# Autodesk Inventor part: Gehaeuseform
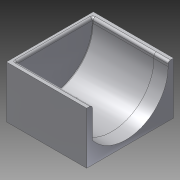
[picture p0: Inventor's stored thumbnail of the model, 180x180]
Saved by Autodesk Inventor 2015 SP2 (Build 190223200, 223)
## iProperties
Created: 2016-01
Part Number: Gehaeuseform
Material: PC/ABS-Kunststoff
Document SubType Name: Modeling
Designer: ryll
Mass: 441.159 g
Surface Area: 1593.78 cm^2
Volume: 1234.8 cm^3
Density: 0.357273 g/cm^3
Appearance: Glatt - weiß
Author: ryll
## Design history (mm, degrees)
sketch "Skizze1"
  geometry: L1 (-71, 0)-(-71, -54.491); L2 (-71, 0)-(-83, 0); L3 (-83, 0)-(-83, -100); L4 (-83, -100)-(101, -100); L5 (101, -100)-(101, 0); L6 (101, 0)-(89.5, 0); L7 (-121.405, 0)-(147.427, 0) reference; L8 (0, 22.399)-(0, -134.393) reference; A1 r 89.5 centre (0, 0) between (-71, -54.491) and (89.5, 0); 1 further point
  constraints: 12 end point, 4 perpendicular, 2 point on circle, 1 centre point, 1 coincident, 1 collinear, 1 horizontal, 1 point on line, 1 vertical
  dimensions: "d0" = 179 diameter of A1; "d1" = 71 distance from line of point (0, 0) L1; "d2" = 100 distance of L4.end L5.end; "d3" = 184 distance between parallel lines of L3 L5; "d4" = 12 distance of L1.start L2.end
extrude "Extrusion1" new body sketch "Skizze1" distance "d5" = 130; taper "d6" = 0 deg
feature "Flächenverjüngung1" dims angle "d7" = 0.01 deg
sketch "Skizze2"
  geometry: L1 (0, 101)-(-100, 101); L2 (-100, 101)-(-100, -83); L3 (-100, -83)-(0, -83); L4 (0, -83)-(0, 101); 1 further point
  constraints: 8 end point, 2 parallel, 1 horizontal, 1 perpendicular
extrude "Extrusion2" join sketch "Skizze2" distance "d8" = 10; taper "d9" = 0 deg
sketch "Skizze3"
  geometry: L1 (54.491, -71)-(0, -71) reference; L2 (0, -71)-(0, -83) reference; L3 (0, -83)-(100, -83) reference; L4 (100, -83)-(100, 101) reference; L5 (100, 101)-(0, 101) reference; L6 (0, 101)-(0, 89.5) reference; A1 r 89.5 centre (0, 0) between (54.491, -71) and (0, 89.5) reference; 1 further point
extrude "Extrusion3" join sketch "Skizze3" distance "d10" = 30; taper "d11" = 0 deg
fillet "Rundung1" dims "d12" = 1
sketch "Skizze4"
  geometry: L1 (11, 172.477)-(140, 172.5) reference; L2 (140, 172.5)-(170, 172.5) reference; L3 (170, 184)-(170, 172.5) reference; L4 (170, 184)-(0, 184) reference; L5 (0, 0)-(0, 184) reference; L6 (170, 0)-(0, 0) reference; L7 (170, 12)-(170, 0) reference; L8 (140, 12)-(170, 12) reference; L9 (11, 12.023)-(140, 12) reference; L10 (10, 13.023)-(10, 171.477) reference; A1 r 1 centre (11, 13.023) between (10, 13.023) and (11, 12.023) reference; A2 r 1 centre (11, 171.477) between (11, 172.477) and (10, 171.477) reference; 1 further point
extrude "Extrusion4" join sketch "Skizze4" distance "d13" = 10; taper "d14" = 0 deg
fillet "Rundung2" dims "d15" = 5
node "Volumenkörper1"
node "Projizierte Kontur1"
node "Projizierte Kontur2"
